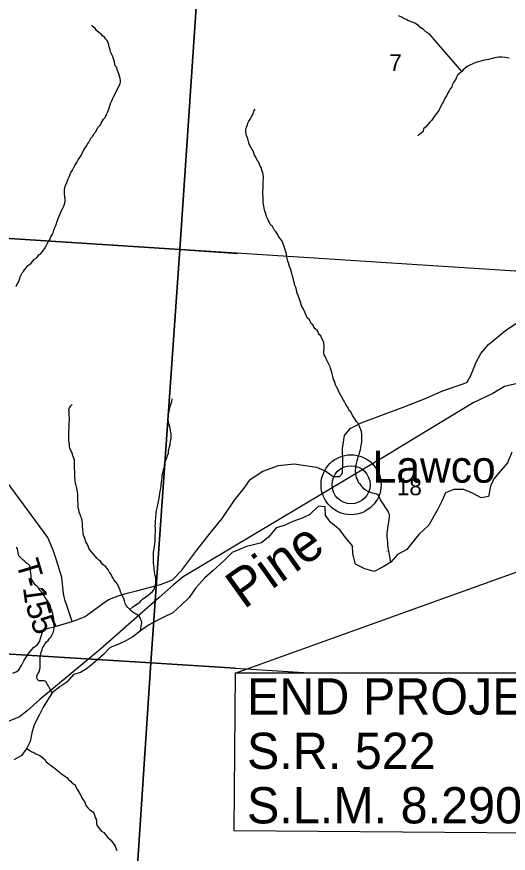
# Model space of a CAD drawing. Extents: x 0 to 82.7, y -0.2 to 22.
# Drawn here: x 5.374 to 6.593, y 16.831 to 18.905 of the extents above; entities that cross this region are included whole.
import ezdxf

# ---------------------------------------------------------------- set-up
doc = ezdxf.new("R2010")
doc.units = 0
for name, color, linetype in [('Default', 7, 'Continuous'), ('GM_X_County_Road', 7, 'Continuous'), ('GM_X_Minor_River', 7, 'Continuous'), ('GM_X_Minor_River_Text', 7, 'Continuous'), ('GM_X_Rail_Line', 7, 'Continuous'), ('GM_X_Section', 7, 'Continuous'), ('GM_X_Section_Text', 7, 'Continuous'), ('GM_X_Township_Road', 7, 'Continuous'), ('GM_X_Township_Road_Text', 7, 'Continuous'), ('GM_X_Unincorporated', 7, 'Continuous'), ('GM_X_Unincorporated_Location', 7, 'Continuous'), ('GM_X_Unincorporated_Text', 7, 'Continuous'), ('SH_Data', 7, 'Continuous')]:
    doc.layers.add(name, color=color, linetype=linetype)

msp = doc.modelspace()

# ---------------------------------------------------------------- linework, layer by layer
at = {"layer": 'Default'}
msp.add_lwpolyline([(5.916, 17.2773), (5.9127, 16.8876), (6.7496, 16.8806), (6.7482, 17.2774)], dxfattribs=at)
at = {"layer": 'GM_X_County_Road'}
msp.add_line((5.4689, 17.3934), (5.5113, 17.4057), dxfattribs=at)
for points in [[(6.2254, 17.8971), (6.228, 17.8985), (6.3326, 17.9376), (6.3894, 17.9596), (6.4281, 17.9767), (6.4614, 17.9881), (6.4811, 17.9953), (6.491, 17.9995), (6.5004, 18.0158), (6.5137, 18.0488), (6.5251, 18.0704), (6.544, 18.0924), (6.5868, 18.1273), (6.6168, 18.1478), (6.6312, 18.1611), (6.655, 18.1676), (6.7047, 18.1592), (6.7488, 18.1415), (6.7681, 18.1337)], [(5.5113, 17.4057), (5.5418, 17.4174), (5.5471, 17.4207), (5.5871, 17.4506), (5.601, 17.4594), (5.612, 17.4642), (5.6251, 17.4697), (5.6478, 17.4763), (5.6708, 17.4822), (5.7305, 17.4974), (5.7605, 17.5093), (5.7835, 17.5327), (5.821, 17.5824), (5.854, 17.6249), (5.8835, 17.6613), (5.9139, 17.7068), (5.9377, 17.7368), (5.9533, 17.7581), (5.9847, 17.7789), (6.0234, 17.7926), (6.0624, 17.7964), (6.1173, 17.7881), (6.1405, 17.7786), (6.159, 17.7657), (6.1742, 17.7653), (6.1821, 17.774), (6.1829, 17.8013), (6.1821, 17.8347), (6.1867, 17.8674), (6.2011, 17.8844), (6.2124, 17.8903), (6.2254, 17.8971)], [(5.3644, 17.2773), (5.374, 17.2815), (5.3787, 17.286), (5.3853, 17.297), (5.3925, 17.3096), (5.4037, 17.3275), (5.4157, 17.3414), (5.4243, 17.3476), (5.4301, 17.3554), (5.4338, 17.3673), (5.4387, 17.383), (5.444, 17.387), (5.4525, 17.389), (5.4689, 17.3934)]]:
    msp.add_lwpolyline(points, dxfattribs=at)
at = {"layer": 'GM_X_Minor_River'}
for points in [[(6.4783, 18.7697), (6.3997, 18.8604), (6.3959, 18.8631), (6.3884, 18.8677), (6.3831, 18.8739), (6.3741, 18.8793), (6.3704, 18.8835), (6.3613, 18.8894), (6.3545, 18.8921), (6.3443, 18.896), (6.3406, 18.8984), (6.3334, 18.9015), (6.3296, 18.9042), (6.3209, 18.9081)], [(5.5757, 18.6314), (5.5818, 18.637), (5.583, 18.6416), (5.5892, 18.6514), (5.5934, 18.6559), (5.5973, 18.6646), (5.5996, 18.6695), (5.6016, 18.6748), (5.6032, 18.679), (5.6063, 18.6899), (5.609, 18.6956), (5.611, 18.7009), (5.6133, 18.7047), (5.6168, 18.7137), (5.6211, 18.7205), (5.623, 18.7254), (5.6265, 18.7307), (5.6304, 18.7398), (5.6312, 18.7436), (5.6313, 18.7477), (5.6306, 18.7519), (5.6291, 18.7584), (5.6269, 18.7638), (5.6258, 18.7683), (5.6236, 18.7725), (5.621, 18.7802), (5.6184, 18.784), (5.6162, 18.7932), (5.6148, 18.7985), (5.6129, 18.8035), (5.6111, 18.8088), (5.6085, 18.8138), (5.6067, 18.8187), (5.6052, 18.8237), (5.6041, 18.8286), (5.6027, 18.8325), (5.602, 18.837), (5.5997, 18.842), (5.5979, 18.8466), (5.5941, 18.8508), (5.5915, 18.855), (5.5866, 18.8581), (5.5829, 18.8623), (5.5784, 18.8658), (5.572, 18.8716), (5.5683, 18.8762), (5.5634, 18.8808), (5.5596, 18.8847)], [(6.5952, 18.8028), (6.5906, 18.8036), (6.5865, 18.8044), (6.5785, 18.8053), (6.5739, 18.8054), (6.569, 18.8054), (6.5595, 18.8036), (6.5542, 18.8018), (6.5504, 18.8011), (6.5439, 18.7993), (6.5401, 18.7986), (6.5336, 18.7975), (6.5253, 18.7953), (6.518, 18.7935), (6.5127, 18.7921), (6.5055, 18.7887), (6.4982, 18.785), (6.4933, 18.7828), (6.4864, 18.778), (6.481, 18.7735), (6.4783, 18.7697), (6.4722, 18.7645), (6.4676, 18.7607), (6.4649, 18.7554), (6.4629, 18.7509), (6.4575, 18.7426), (6.4544, 18.7358), (6.4532, 18.7316), (6.449, 18.7264), (6.447, 18.7215), (6.4428, 18.7154), (6.4404, 18.7094), (6.4347, 18.7015)], [(6.4347, 18.7015), (6.4323, 18.6951), (6.4284, 18.689), (6.4265, 18.6852), (6.4218, 18.6743), (6.4183, 18.6698), (6.4141, 18.6649), (6.4106, 18.6585), (6.4037, 18.6487), (6.3983, 18.6438), (6.3937, 18.6382), (6.3876, 18.6318), (6.3833, 18.6273), (6.3821, 18.6212), (6.3768, 18.6167), (6.3729, 18.6133), (6.3691, 18.6104)], [(6.0886, 18.1728), (6.0842, 18.1823), (6.0808, 18.1873), (6.0768, 18.1999), (6.072, 18.2144), (6.0691, 18.2213), (6.0687, 18.2251), (6.0662, 18.2338), (6.064, 18.2388), (6.0618, 18.2464), (6.0603, 18.2537), (6.0574, 18.2651), (6.0563, 18.2689), (6.0534, 18.2807), (6.0508, 18.2861), (6.0483, 18.2949), (6.0464, 18.2991), (6.0446, 18.3056), (6.0432, 18.3151), (6.0421, 18.3196), (6.041, 18.3246), (6.0388, 18.3303), (6.0374, 18.3357), (6.0344, 18.3425), (6.0315, 18.3506), (6.027, 18.3559), (6.0233, 18.3609), (6.0207, 18.3663), (6.0162, 18.3735), (6.0121, 18.3774), (6.0084, 18.3854), (6.0046, 18.3889), (6.0013, 18.3954), (5.9983, 18.3996), (5.9957, 18.4053), (5.9931, 18.4099), (5.9902, 18.4217), (5.9884, 18.4267), (5.9862, 18.44), (5.9852, 18.4457), (5.9849, 18.4594), (5.9846, 18.4651), (5.9847, 18.4731), (5.9852, 18.4792), (5.9856, 18.4841), (5.9853, 18.4891), (5.9853, 18.4929), (5.9854, 18.4982), (5.9858, 18.505), (5.9859, 18.5092), (5.9845, 18.518), (5.983, 18.5225), (5.9805, 18.5313), (5.9778, 18.5351), (5.9742, 18.5447), (5.9708, 18.5485), (5.9671, 18.5573), (5.9641, 18.5619), (5.9604, 18.5726), (5.9578, 18.5764), (5.9549, 18.5822), (5.9515, 18.5875), (5.9493, 18.5929), (5.9468, 18.6028), (5.9438, 18.6108), (5.9431, 18.6154), (5.9424, 18.6207), (5.9421, 18.6249), (5.9441, 18.6317), (5.946, 18.637), (5.9468, 18.6415), (5.9499, 18.6461), (5.953, 18.6517), (5.9569, 18.6585), (5.9596, 18.6634), (5.9623, 18.6714), (5.9654, 18.6759)], [(5.3723, 18.2362), (5.3739, 18.2404), (5.3778, 18.2475), (5.3801, 18.2517), (5.3817, 18.2566), (5.3825, 18.2604), (5.3871, 18.2702), (5.3906, 18.274), (5.3933, 18.2777), (5.3971, 18.283), (5.401, 18.2886), (5.4086, 18.2939), (5.4179, 18.3044), (5.4236, 18.3077), (5.429, 18.3149), (5.4336, 18.3182), (5.4386, 18.3239), (5.444, 18.3322), (5.4475, 18.3386), (5.4521, 18.3473), (5.4552, 18.351), (5.4583, 18.3593), (5.4607, 18.3635), (5.4638, 18.3695), (5.4661, 18.3763), (5.4681, 18.3828), (5.4704, 18.3877), (5.4724, 18.3926), (5.4732, 18.3964), (5.4751, 18.4002), (5.4763, 18.4051), (5.479, 18.4111), (5.4814, 18.4168), (5.4845, 18.4251), (5.488, 18.4304), (5.4899, 18.4342), (5.4911, 18.4383), (5.4931, 18.4436), (5.4939, 18.4478), (5.4939, 18.452), (5.4933, 18.4596), (5.4922, 18.4657), (5.4919, 18.4695), (5.4923, 18.4767), (5.4951, 18.4877), (5.4978, 18.4933), (5.5014, 18.5039), (5.5041, 18.5088), (5.508, 18.5194), (5.5118, 18.5247), (5.5146, 18.53), (5.5177, 18.5364), (5.5231, 18.5439), (5.5258, 18.5507), (5.5304, 18.556), (5.5327, 18.5602), (5.5378, 18.57), (5.5405, 18.5756), (5.5436, 18.5805), (5.5467, 18.5843), (5.5482, 18.5885), (5.5517, 18.593), (5.5544, 18.5975), (5.5579, 18.6043), (5.5618, 18.6084), (5.5656, 18.6156), (5.5695, 18.6193), (5.5757, 18.6314)], [(6.3018, 17.5537), (6.3021, 17.5529), (6.2944, 17.5938), (6.2941, 17.5995), (6.2941, 17.6044), (6.2934, 17.6086), (6.2928, 17.6174), (6.2928, 17.6246), (6.2933, 17.6287), (6.2941, 17.6382), (6.2949, 17.642), (6.2958, 17.6481), (6.297, 17.6519), (6.2982, 17.6598), (6.2986, 17.664), (6.2983, 17.6709), (6.2965, 17.6758), (6.2943, 17.6804), (6.292, 17.6846), (6.2887, 17.6888), (6.2838, 17.6965), (6.2793, 17.7026), (6.2767, 17.7072), (6.2749, 17.7118), (6.2719, 17.7172), (6.2674, 17.7214), (6.2606, 17.7234), (6.2561, 17.7242), (6.25, 17.7266), (6.2462, 17.7277), (6.2406, 17.7309), (6.2346, 17.7351), (6.2319, 17.739), (6.2267, 17.7455), (6.2226, 17.7489), (6.2189, 17.7581), (6.2167, 17.7619), (6.2153, 17.773), (6.2146, 17.7775), (6.2151, 17.7886), (6.2171, 17.7976), (6.2183, 17.8045), (6.2199, 17.8102), (6.2218, 17.817), (6.2242, 17.8226), (6.2254, 17.8272), (6.2266, 17.8313), (6.2274, 17.8378), (6.2294, 17.8461), (6.2298, 17.8503), (6.23, 17.8689), (6.229, 17.8769), (6.2275, 17.8811), (6.2253, 17.8876), (6.2235, 17.8922), (6.2197, 17.8983), (6.2164, 17.9021), (6.2112, 17.911), (6.2078, 17.9152), (6.2026, 17.9259), (6.1989, 17.9293), (6.1959, 17.9355), (6.1903, 17.9439), (6.1877, 17.9485), (6.1847, 17.9546), (6.1792, 17.9638), (6.1762, 17.9695), (6.1732, 17.9749), (6.171, 17.9806), (6.1669, 17.9879), (6.1643, 17.9929), (6.1618, 18.002), (6.1599, 18.0062), (6.1577, 18.0135), (6.1563, 18.0199), (6.1541, 18.0291), (6.1523, 18.0337), (6.1515, 18.0375), (6.1478, 18.044), (6.146, 18.0486), (6.1426, 18.0551), (6.1404, 18.0593), (6.1386, 18.0631), (6.1367, 18.0673), (6.136, 18.073), (6.1362, 18.0867), (6.1366, 18.0909), (6.1348, 18.1004), (6.1311, 18.1076), (6.1285, 18.1138), (6.1248, 18.1168), (6.1222, 18.1211), (6.1196, 18.1268), (6.1143, 18.1314), (6.1113, 18.136), (6.108, 18.1414), (6.1042, 18.1448), (6.099, 18.1552), (6.0945, 18.159), (6.0905, 18.1689), (6.0886, 18.1728)], [(5.6541, 17.4355), (5.6621, 17.4418), (5.6663, 17.4448), (5.6743, 17.4504), (5.6789, 17.453), (5.682, 17.4568), (5.6855, 17.4609), (5.6943, 17.4673), (5.6996, 17.471), (5.7057, 17.4759), (5.7104, 17.4804), (5.7138, 17.4845), (5.7158, 17.4883), (5.7169, 17.4924), (5.7181, 17.497), (5.719, 17.5031), (5.719, 17.5099), (5.7187, 17.5137), (5.7176, 17.5198), (5.7165, 17.5244), (5.7155, 17.5301), (5.7148, 17.535), (5.7144, 17.5392), (5.7141, 17.5438), (5.7135, 17.5518), (5.7132, 17.559), (5.7128, 17.5635), (5.7129, 17.573), (5.7134, 17.5776), (5.7146, 17.5856), (5.7154, 17.5897), (5.7167, 17.5996), (5.7171, 17.6053), (5.7176, 17.6117), (5.7178, 17.6364), (5.7176, 17.644), (5.718, 17.6486), (5.718, 17.6543), (5.7185, 17.6626), (5.7198, 17.6759), (5.7206, 17.6812), (5.723, 17.6911), (5.7243, 17.6994), (5.7271, 17.7115), (5.7295, 17.729), (5.7315, 17.7358), (5.732, 17.7419), (5.7332, 17.7533), (5.7344, 17.7593), (5.7349, 17.7631), (5.7349, 17.7688), (5.7361, 17.7734), (5.7385, 17.7851), (5.7401, 17.7896), (5.7405, 17.7934), (5.7429, 17.804), (5.7456, 17.8089), (5.7476, 17.8177), (5.75, 17.8233), (5.7504, 17.8283), (5.7532, 17.8392), (5.7544, 17.8438), (5.7556, 17.854), (5.7568, 17.8593), (5.7573, 17.8662), (5.757, 17.8707), (5.7559, 17.8753), (5.7545, 17.8841), (5.7534, 17.8883), (5.7519, 17.8932), (5.7508, 17.8978), (5.7501, 17.9016), (5.7494, 17.9058), (5.7491, 17.9107), (5.75, 17.9225), (5.7519, 17.927), (5.7527, 17.9312), (5.7539, 17.9376), (5.7559, 17.9429), (5.7571, 17.9475), (5.7583, 17.9516), (5.7595, 17.9577)], [(5.6809, 17.383), (5.684, 17.4036), (5.6837, 17.4074), (5.6811, 17.4123), (5.6796, 17.4162), (5.6766, 17.42), (5.6702, 17.4239), (5.6665, 17.4258), (5.6627, 17.4282), (5.6586, 17.4316), (5.6541, 17.4355), (5.6496, 17.4401), (5.6454, 17.4451), (5.6432, 17.4501), (5.641, 17.4569), (5.6392, 17.463), (5.6362, 17.4684), (5.634, 17.4741), (5.6314, 17.4791), (5.6307, 17.4833), (5.627, 17.4909), (5.6241, 17.4982), (5.6199, 17.5032), (5.6151, 17.5093), (5.6132, 17.5135), (5.6099, 17.5181), (5.608, 17.5223), (5.6032, 17.5285), (5.6006, 17.5342), (5.5953, 17.5403), (5.5916, 17.5434), (5.5878, 17.5473), (5.5841, 17.5515), (5.5815, 17.5553), (5.5777, 17.5577), (5.5728, 17.5627), (5.5691, 17.5669), (5.565, 17.5723), (5.5597, 17.5788), (5.5552, 17.5834), (5.5526, 17.588), (5.5501, 17.5949), (5.5456, 17.6037), (5.543, 17.6113), (5.5397, 17.6197), (5.5383, 17.6239), (5.5376, 17.6357), (5.5369, 17.641), (5.537, 17.6463), (5.5363, 17.6558), (5.5349, 17.6604), (5.533, 17.665), (5.5312, 17.6715), (5.5286, 17.6768), (5.5275, 17.6825), (5.5265, 17.6875), (5.5258, 17.6921), (5.5262, 17.6981), (5.5255, 17.7031), (5.5256, 17.7084), (5.5253, 17.7164), (5.525, 17.7217), (5.5243, 17.7267), (5.5239, 17.7324), (5.5225, 17.7362), (5.521, 17.7434), (5.52, 17.7476), (5.5189, 17.756), (5.5179, 17.764), (5.5176, 17.772), (5.5177, 17.7788), (5.5173, 17.7849), (5.5175, 17.8001), (5.5172, 17.8046), (5.5157, 17.8107), (5.5132, 17.8168), (5.5121, 17.8207), (5.5102, 17.826), (5.508, 17.8298), (5.5058, 17.8352), (5.5051, 17.8394), (5.5044, 17.8462), (5.503, 17.8538), (5.503, 17.8603), (5.5027, 17.8641), (5.5028, 17.8679), (5.5032, 17.874), (5.5033, 17.8789), (5.5037, 17.8861), (5.5042, 17.8918), (5.5044, 17.9104), (5.5041, 17.9176), (5.5038, 17.923), (5.5038, 17.9271), (5.5031, 17.9317), (5.5047, 17.9359), (5.507, 17.94), (5.5112, 17.9438)], [(6.6023, 17.8259), (6.5912, 17.7994), (6.5759, 17.7812), (6.5575, 17.7593), (6.5491, 17.7411), (6.544, 17.7161), (6.5257, 17.7124), (6.5042, 17.7239), (6.483, 17.7327), (6.4584, 17.7328), (6.4378, 17.7246), (6.4294, 17.7056), (6.4186, 17.6844), (6.4086, 17.6666), (6.3963, 17.6447), (6.3715, 17.6213), (6.3563, 17.6031), (6.3413, 17.5846), (6.3185, 17.5718), (6.3021, 17.5529), (6.2826, 17.5412), (6.2606, 17.53), (6.2375, 17.5365), (6.2144, 17.548), (6.2074, 17.5735), (6.2068, 17.5936), (6.1887, 17.615), (6.1759, 17.6325), (6.1533, 17.6509), (6.1402, 17.6688), (6.1392, 17.6904), (6.1221, 17.6917), (6.1011, 17.6713), (6.0817, 17.6619), (6.0585, 17.6536), (6.0372, 17.6439), (6.0171, 17.6383), (5.9987, 17.6152), (5.9808, 17.6009), (5.9611, 17.5957), (5.944, 17.592), (5.9265, 17.5841), (5.9082, 17.577), (5.8876, 17.5566), (5.8609, 17.5324), (5.8403, 17.5143), (5.8185, 17.489), (5.8017, 17.4651), (5.7826, 17.447), (5.7608, 17.4274), (5.7391, 17.4161), (5.722, 17.4086), (5.7011, 17.3966), (5.6809, 17.383), (5.6615, 17.3675), (5.6432, 17.357), (5.6227, 17.348), (5.6052, 17.3416), (5.5891, 17.3235)], [(5.4617, 17.2292), (5.4618, 17.2289), (5.4456, 17.2573), (5.4415, 17.2589), (5.4373, 17.2589), (5.4331, 17.2582), (5.4289, 17.2583), (5.4241, 17.2625), (5.4238, 17.2693), (5.4257, 17.2743), (5.4292, 17.2807), (5.4312, 17.2863), (5.432, 17.2928), (5.4321, 17.3004), (5.4318, 17.3053), (5.4319, 17.3141), (5.4331, 17.3213), (5.4347, 17.3296), (5.437, 17.3353), (5.4379, 17.3402), (5.4398, 17.344), (5.4437, 17.3496), (5.4479, 17.3553), (5.4517, 17.3583), (5.4544, 17.3628), (5.459, 17.3681), (5.4606, 17.3722), (5.4633, 17.3767), (5.4649, 17.3805), (5.4661, 17.3851), (5.4673, 17.3915), (5.467, 17.3968), (5.4663, 17.4025), (5.466, 17.4079), (5.4656, 17.4128), (5.4646, 17.4185), (5.4635, 17.4246), (5.4609, 17.433), (5.4595, 17.4368), (5.4576, 17.4437), (5.4554, 17.4494), (5.4521, 17.4548), (5.4487, 17.4598), (5.4439, 17.4663), (5.4416, 17.4705), (5.4364, 17.4785), (5.4323, 17.4824), (5.4278, 17.4889), (5.4233, 17.4931), (5.4196, 17.497), (5.4166, 17.502), (5.4125, 17.5066), (5.4102, 17.5108), (5.4095, 17.515), (5.4092, 17.5192), (5.4085, 17.5252), (5.4082, 17.5306), (5.4079, 17.5351), (5.4075, 17.5397), (5.4064, 17.5439), (5.4023, 17.5481), (5.397, 17.5516), (5.3933, 17.5551), (5.3892, 17.5589), (5.3839, 17.5639), (5.3794, 17.5682), (5.3779, 17.5731), (5.3772, 17.5769), (5.3769, 17.5819), (5.3754, 17.5857), (5.3736, 17.5903)], [(6.2923, 17.5805), (6.2925, 17.5801)], [(5.5891, 17.3235), (5.5685, 17.3058), (5.5495, 17.2899), (5.5323, 17.279), (5.5148, 17.2741), (5.4977, 17.2556), (5.4805, 17.2439), (5.4618, 17.2289), (5.4499, 17.2103), (5.4392, 17.1929), (5.4296, 17.1736), (5.4173, 17.1494), (5.4115, 17.13), (5.4068, 17.108), (5.3979, 17.0898), (5.3849, 17.0725), (5.3663, 17.0631)], [(5.3984, 17.0916), (5.4042, 17.0876), (5.411, 17.0826), (5.4148, 17.0814), (5.4212, 17.0779), (5.4253, 17.0756), (5.4295, 17.074), (5.4332, 17.0717), (5.4389, 17.0674), (5.4434, 17.0639), (5.4471, 17.0578), (5.4546, 17.0516), (5.4592, 17.0489), (5.464, 17.0443), (5.4693, 17.0416), (5.4738, 17.0373), (5.481, 17.0312), (5.4851, 17.0277), (5.4934, 17.0219), (5.4983, 17.0188), (5.5016, 17.0149), (5.5073, 17.0099), (5.5125, 17.0042), (5.5167, 17.0014), (5.5196, 16.9976), (5.5248, 16.988), (5.5293, 16.98), (5.5319, 16.9762), (5.5341, 16.9705), (5.5386, 16.9636), (5.542, 16.9593), (5.5464, 16.9486), (5.5498, 16.944), (5.555, 16.939), (5.5618, 16.9348), (5.5655, 16.9286), (5.5688, 16.9199), (5.571, 16.9153), (5.5717, 16.9096), (5.5721, 16.905), (5.5731, 16.8989), (5.5769, 16.8947), (5.5799, 16.8908), (5.5844, 16.8862), (5.5896, 16.8827), (5.5949, 16.8762), (5.6005, 16.8693), (5.6046, 16.8662), (5.6087, 16.8612), (5.6121, 16.8566), (5.6155, 16.8528), (5.6181, 16.8486), (5.6195, 16.8436), (5.622, 16.8375)]]:
    msp.add_lwpolyline(points, dxfattribs=at)
at = {"layer": 'GM_X_Rail_Line'}
msp.add_lwpolyline([(7.3273, 17.7066), (7.3259, 17.7432), (7.3159, 17.7619), (7.3005, 17.7817), (7.283, 17.7916), (6.9482, 17.9012), (6.7526, 17.9674), (6.7006, 17.9857), (6.665, 17.9956), (6.6225, 17.9973), (6.584, 17.9881), (6.5551, 17.9713), (6.5062, 17.9483), (6.3111, 17.8299), (6.3099, 17.8288), (5.7871, 17.5166), (5.7628, 17.4965), (5.7274, 17.4651), (5.5819, 17.3372), (5.4314, 17.2126), (5.3996, 17.1841), (5.3803, 17.1691), (5.3466, 17.155)], dxfattribs=at)
at = {"layer": 'GM_X_Section'}
for points in [[(4.8277, 19.4092), (5.8471, 19.3468), (5.7783, 18.3279), (4.7658, 18.3936)], [(5.8471, 19.3468), (6.8524, 19.275), (6.7772, 18.2637), (5.7783, 18.3279)], [(4.7658, 18.3936), (5.7783, 18.3279), (5.7068, 17.3032), (4.7026, 17.3656)], [(4.7026, 17.3656), (5.7068, 17.3032), (5.6394, 16.2869), (4.6367, 16.3423)]]:
    msp.add_lwpolyline(points, close=True, dxfattribs=at)
for points in [[(5.9155, 17.29), (5.7068, 17.3032), (5.7783, 18.3279), (5.9225, 18.3186)], [(6.6791, 16.7901), (6.6409, 16.2254), (5.6394, 16.2869), (5.7068, 17.3032), (6.099, 17.2784)]]:
    msp.add_lwpolyline(points, dxfattribs=at)
at = {"layer": 'GM_X_Township_Road'}
msp.add_line((5.4689, 17.3934), (5.5113, 17.4057), dxfattribs=at)
for points in [[(5.4722, 17.5578), (5.4644, 17.583), (5.451, 17.6143), (5.3499, 17.7511), (5.2837, 17.842), (5.1514, 17.9826), (5.008, 18.1425), (4.8895, 18.2501), (4.7957, 18.341), (4.6965, 18.4651)], [(5.5113, 17.4057), (5.498, 17.4458), (5.4928, 17.4592), (5.4901, 17.4748), (5.4856, 17.5147), (5.4722, 17.5578)]]:
    msp.add_lwpolyline(points, dxfattribs=at)
at = {"layer": 'GM_X_Unincorporated'}
for radius in [0.0744, 0.0472]:
    msp.add_circle((6.2032, 17.7448), radius, dxfattribs=at)
at = {"layer": 'GM_X_Unincorporated_Location'}
msp.add_line((6.2032, 17.7448), (6.2032, 17.7448), dxfattribs=at)
at = {"layer": 'SH_Data'}
msp.add_lwpolyline([(5.9155, 17.2774), (7.413, 17.816), (6.7482, 17.2774)], close=True, dxfattribs=at)

# ---------------------------------------------------------------- texts
at = {"layer": 'Default'}
for s, p in [('END PROJECT', (5.945, 17.175)), ('S.R. 522 ', (5.945, 17.04)), ('S.L.M. 8.290', (5.945, 16.905))]:
    msp.add_text(s, height=0.09, dxfattribs=at).set_placement(p)
at = {"layer": 'GM_X_Minor_River_Text'}
msp.add_text('Pine', height=0.09469, rotation=35.4888, dxfattribs=at).set_placement((5.9372, 17.4347))
at = {"layer": 'GM_X_Section_Text'}
for s, height, p in [('7', 0.0419, (6.298, 18.7706)), ('18', 0.04186, (6.3167, 17.7188))]:
    msp.add_text(s, height=height, rotation=0, dxfattribs=at).set_placement(p)
at = {"layer": 'GM_X_Township_Road_Text'}
for s, rotation, p in [('T', 286.7366, (5.3716, 17.5511)), ('-', 283.7617, (5.3837, 17.5112)), ('1', 277.9826, (5.3889, 17.49)), ('5', 285.466, (5.3954, 17.4474)), ('5', 290.722, (5.4065, 17.4083))]:
    msp.add_text(s, height=0.0568, rotation=rotation, dxfattribs=at).set_placement(p)
at = {"layer": 'GM_X_Unincorporated_Text'}
msp.add_text('Lawco', height=0.07898, rotation=0, dxfattribs=at).set_placement((6.2567, 17.75))

doc.saveas('drawing.dxf')
